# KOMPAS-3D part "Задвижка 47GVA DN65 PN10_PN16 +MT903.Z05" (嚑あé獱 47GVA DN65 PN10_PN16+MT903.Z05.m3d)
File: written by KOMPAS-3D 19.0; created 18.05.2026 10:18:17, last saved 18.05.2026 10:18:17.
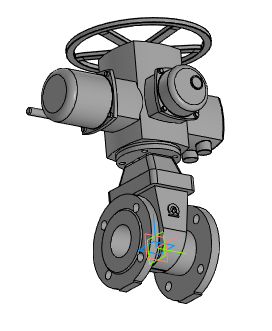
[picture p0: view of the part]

Document properties: Автор: Энергия; Полное имя файла: ..\Задвижка 47GVA DN50_DN1000+MT903.Z\Задвижка 47GVA DN65 PN10_PN16+MT903.Z05.a3d

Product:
- Part/product: Задвижка 47GVA DN65 PN10_PN16 +MT903.Z05
    Масса: 72.6913
  - Body: Электропривод MT903.Z05-15
      Масса: 49.8062
  - Body: Задвижка 47GVA DN65 PN10_PN16 без исполнит. мех.
      Масса: 22.8851

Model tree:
1. Операция без истории:1
2. Операция без истории:2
